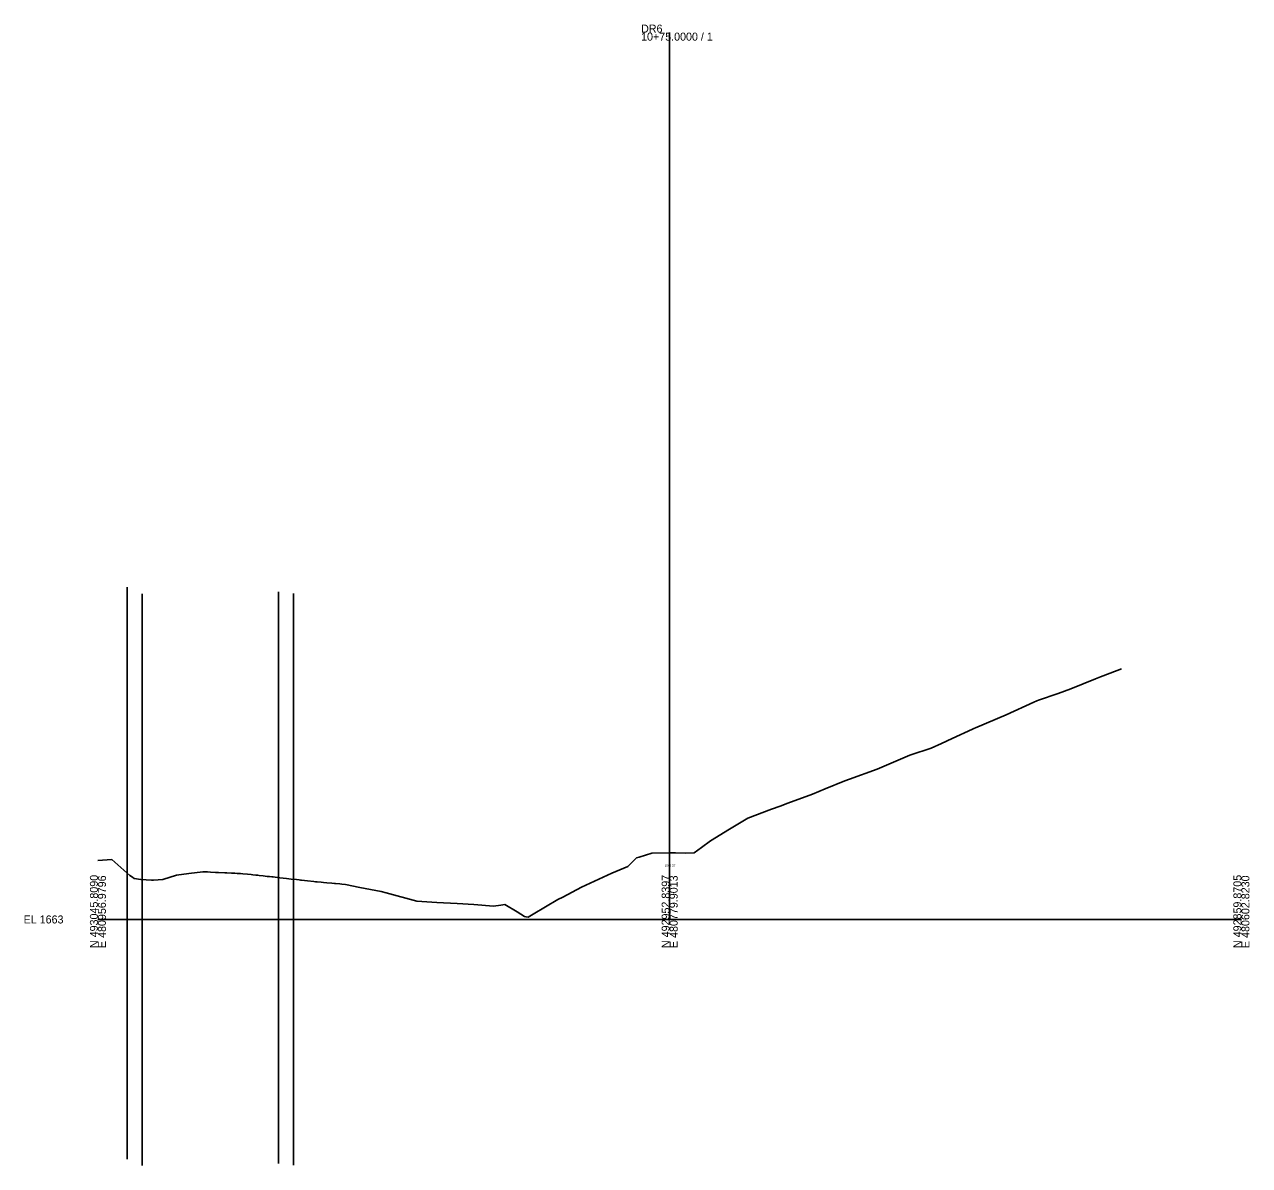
# Model space of a CAD drawing. Extents: x -26 to 403, y -88 to 5647.
# Drawn here: x -25.7 to 402.8, y 1413.9 to 1813 of the extents above; entities that cross this region are included whole.
import ezdxf

# ---------------------------------------------------------------- set-up
doc = ezdxf.new("R2010")
doc.units = 0
for name, color, linetype in [('Exist Cross Section Cell', 7, 'Continuous'), ('Exist XS Center Line Elevation Label', 7, 'Continuous'), ('Exist XS Ground Line', 7, 'Continuous'), ('Scratch_Level_7', 7, 'Continuous')]:
    doc.layers.add(name, color=color, linetype=linetype)

msp = doc.modelspace()

# ---------------------------------------------------------------- linework, layer by layer
at = {"layer": 'Exist Cross Section Cell'}
for p, q in [((200, 1500), (200, 1810.19)), ((0, 1500), (200, 1500)), ((200, 1500), (400, 1500))]:
    msp.add_line(p, q, dxfattribs=at)
at = {"layer": 'Exist XS Ground Line'}
msp.add_lwpolyline([(0, 1520.64), (4.9, 1520.94), (11.21, 1515.36), (12.05, 1514.81), (12.65, 1514.36), (15, 1513.97), (18.68, 1513.72), (19.44, 1513.71), (22.7, 1513.92), (27.51, 1515.47), (31.84, 1516.05), (36.68, 1516.7), (38.34, 1516.63), (39.39, 1516.57), (41.16, 1516.48), (42.23, 1516.43), (44.44, 1516.32), (45.05, 1516.29), (46.68, 1516.22), (47.87, 1516.17), (48.66, 1516.13), (49.15, 1516.11), (49.83, 1516.06), (50.7, 1516), (52.27, 1515.86), (53.56, 1515.71), (54.13, 1515.65), (55.19, 1515.53), (55.98, 1515.44), (56.4, 1515.39), (57.83, 1515.23), (59.22, 1515.07), (60.07, 1514.99), (60.78, 1514.91), (61.28, 1514.86), (62.03, 1514.77), (63.65, 1514.59), (64.83, 1514.46), (65.91, 1514.33), (67.61, 1514.14), (69.48, 1513.92), (70.4, 1513.81), (70.88, 1513.76), (71.25, 1513.72), (72.27, 1513.6), (73.31, 1513.48), (75.5, 1513.27), (76.11, 1513.21), (76.64, 1513.16), (78.1, 1513.02), (78.94, 1512.94), (80.03, 1512.82), (81.86, 1512.66), (82.76, 1512.6), (83.07, 1512.57), (84.63, 1512.42), (85.28, 1512.34), (86.64, 1512.2), (91.58, 1511.21), (99.02, 1509.72), (100.86, 1509.33), (111.53, 1506.44), (118.58, 1505.97), (125.7, 1505.61), (131.48, 1505.19), (138.35, 1504.64), (140.93, 1504.95), (142.32, 1505.23), (146.64, 1502.68), (149.24, 1501.03), (149.73, 1500.97), (150.55, 1500.79), (152.26, 1501.89), (160.85, 1506.99), (162.57, 1507.81), (169.16, 1511.27), (179.81, 1516.22), (185.41, 1518.48), (185.95, 1519.08), (188.4, 1521.5), (189.32, 1521.74), (193.78, 1523.14), (200, 1523.27), (202.08, 1523.32), (205.53, 1523.24), (208.56, 1523.33), (211.1, 1525.15), (214.29, 1527.45), (220.9, 1531.61), (227.37, 1535.38), (235.67, 1538.52), (238.67, 1539.65), (241.38, 1540.67), (249.96, 1543.88), (254.42, 1545.73), (261.26, 1548.54), (262.9, 1549.1), (272.56, 1552.52), (283.24, 1557.11), (284.05, 1557.45), (284.41, 1557.57), (291.45, 1559.93), (295.15, 1561.52), (298.86, 1563.35), (305.93, 1566.59), (306.45, 1566.83), (307.02, 1567.07), (317.74, 1571.58), (327.45, 1576.02), (328.49, 1576.49), (329.04, 1576.68), (335.9, 1578.99), (340.34, 1580.68), (348.96, 1584.15), (350.71, 1584.92), (351.63, 1585.27), (358.12, 1587.68)], dxfattribs=at)
at = {"layer": 'Scratch_Level_7'}
for p, q in [((10.27, 1616.2), (10.27, 1416.2)), ((15.44, 1613.94), (15.44, 1413.94)), ((63.19, 1614.64), (63.19, 1414.64)), ((68.43, 1614.04), (68.43, 1414.04))]:
    msp.add_line(p, q, dxfattribs=at)

# ---------------------------------------------------------------- texts
at = {"layer": 'Exist Cross Section Cell'}
for s, p in [('DR6', (190, 1810.19)), ('10+75.0000 / 1', (190, 1807.39)), ('EL 1663', (-26, 1498.6))]:
    msp.add_text(s, height=2.8, dxfattribs=at).set_placement(p)
for s, p in [('N 493045.8090', (0, 1490)), ('E 480956.9796', (2.8, 1490)), ('N 492952.8397', (200, 1490)), ('E 480779.9013', (202.8, 1490)), ('N 492859.8705', (400, 1490)), ('E 480602.8230', (402.8, 1490))]:
    msp.add_text(s, height=2.8, rotation=90, dxfattribs=at).set_placement(p)
at = {"layer": 'Exist XS Center Line Elevation Label'}
msp.add_text('1686.27', height=0.75, dxfattribs=at).set_placement((198.26, 1518.52))

doc.saveas('drawing.dxf')
